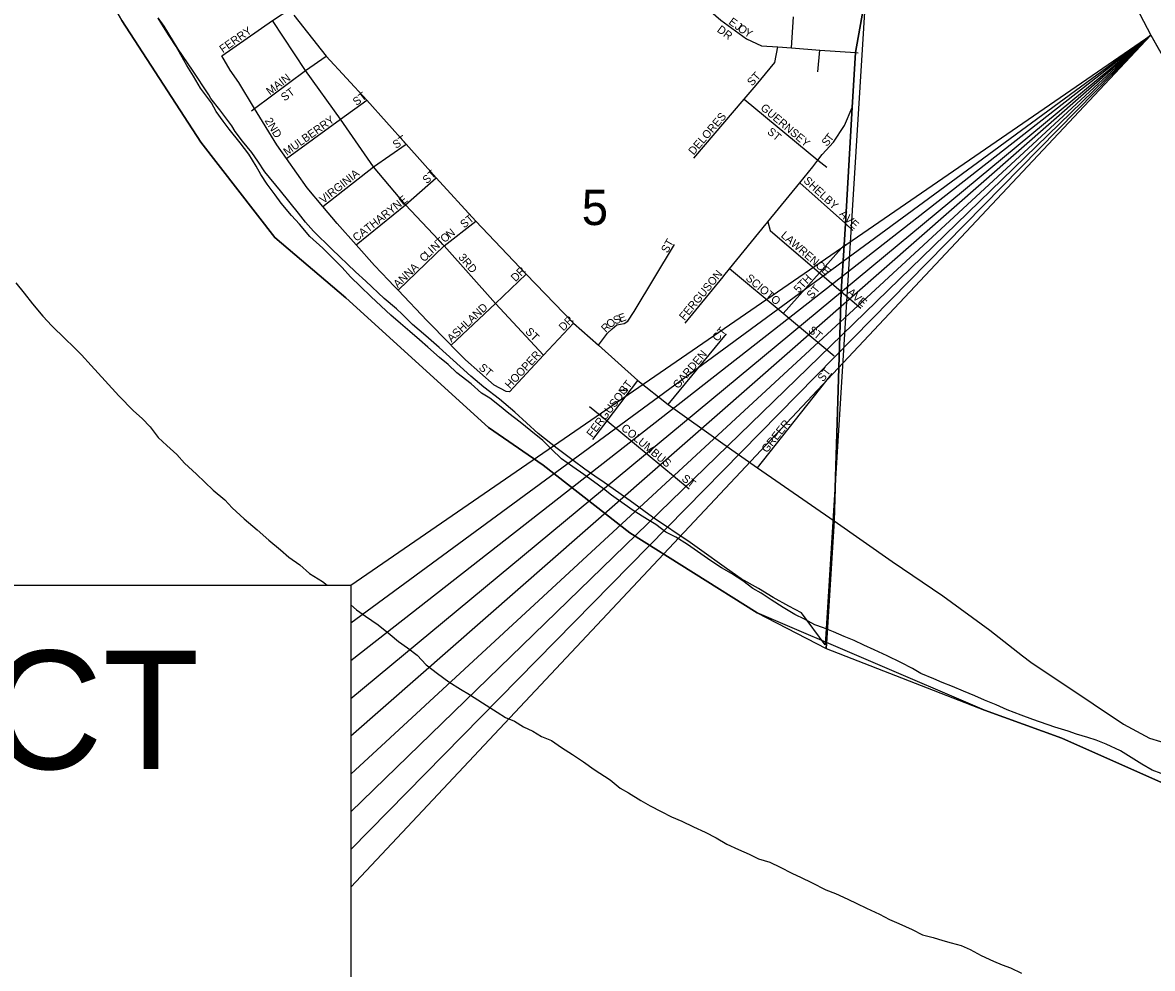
# Model space of a CAD drawing. Extents: x 0 to 34, y 0 to 22.
# Drawn here: x 3.579 to 4.916, y 14.797 to 15.917 of the extents above; entities that cross this region are included whole.
import ezdxf

# ---------------------------------------------------------------- set-up
doc = ezdxf.new("R2010")
doc.units = 0
for name, color, linetype in [('GM_X_City_Street', 7, 'Continuous'), ('GM_X_City_Street_Text', 7, 'Continuous'), ('GM_X_Corporation', 7, 'Continuous'), ('GM_X_County', 7, 'Continuous'), ('GM_X_Major_River', 7, 'Continuous'), ('GM_X_Section', 7, 'Continuous'), ('GM_X_Section_Text', 7, 'Continuous'), ('GM_X_Township', 7, 'Continuous'), ('GM_X_US_Route', 7, 'Continuous'), ('SH_Text', 7, 'Continuous')]:
    doc.layers.add(name, color=color, linetype=linetype)

msp = doc.modelspace()

# ---------------------------------------------------------------- linework, layer by layer
at = {"layer": 'GM_X_City_Street'}
for points in [[(4.3709, 15.9869), (4.3707, 15.96), (4.3788, 15.9425), (4.4051, 15.9194), (4.4355, 15.8973), (4.4532, 15.8892), (4.4727, 15.8878), (4.4889, 15.8866), (4.5222, 15.8842), (4.5644, 15.8812), (4.5676, 15.8809)], [(3.8147, 15.8773), (3.8747, 15.9191), (3.8963, 15.9332)], [(3.8997, 15.9253), (3.9381, 15.877), (3.9864, 15.8247), (4.0329, 15.7727), (4.0682, 15.7327), (4.1153, 15.6817), (4.1747, 15.6187), (4.2308, 15.5607), (4.2604, 15.5348), (4.3071, 15.4929), (4.3427, 15.4647), (4.4074, 15.4185), (4.4485, 15.3898), (4.5393, 15.3267), (4.6081, 15.2788), (4.668, 15.2381), (4.7235, 15.1974), (4.7623, 15.1671)], [(4.1954, 15.5228), (4.1384, 15.584), (4.0776, 15.6526), (4.0321, 15.7008), (3.994, 15.746), (3.9551, 15.8022), (3.9135, 15.8599), (3.8747, 15.9191)], [(4.4889, 15.8866), (4.4912, 15.9233)], [(4.3731, 15.756), (4.4328, 15.8259), (4.447, 15.8425), (4.4693, 15.8696), (4.4727, 15.8878)], [(4.0119, 15.6118), (3.9954, 15.6292), (3.9737, 15.6535), (3.9513, 15.6787), (3.9343, 15.6989), (3.9158, 15.7209), (3.8912, 15.7556), (3.8796, 15.7719), (3.8534, 15.815), (3.8349, 15.8456), (3.8245, 15.8605), (3.8147, 15.8773)], [(3.8499, 15.8124), (3.8534, 15.815), (3.9135, 15.8599), (3.9381, 15.877)], [(4.52, 15.8583), (4.5222, 15.8842)], [(3.8912, 15.7556), (3.9551, 15.8022), (3.9864, 15.8247)], [(4.4328, 15.8259), (4.5202, 15.754), (4.5307, 15.7454)], [(4.4598, 15.6794), (4.461, 15.6809), (4.4986, 15.727), (4.514, 15.746), (4.5202, 15.754), (4.5252, 15.7606), (4.5387, 15.7753), (4.5514, 15.7949), (4.5608, 15.816)], [(3.9343, 15.6989), (3.994, 15.746), (4.0329, 15.7727)], [(3.9737, 15.6535), (4.0321, 15.7008), (4.0682, 15.7327)], [(4.4986, 15.727), (4.5526, 15.6787), (4.5616, 15.6705)], [(4.0233, 15.5998), (4.0776, 15.6526), (4.1153, 15.6817)], [(4.4088, 15.617), (4.4154, 15.625), (4.459, 15.6785), (4.4598, 15.6794)], [(4.461, 15.6809), (4.4634, 15.6706), (4.5219, 15.6205), (4.5478, 15.5982), (4.5707, 15.5785)], [(4.2604, 15.5348), (4.2711, 15.549), (4.2765, 15.5542), (4.2822, 15.5589), (4.2909, 15.5606), (4.2951, 15.5633), (4.3027, 15.5747), (4.3502, 15.654)], [(4.4789, 15.5722), (4.5219, 15.6205), (4.5511, 15.6533), (4.5523, 15.6547)], [(4.0861, 15.5347), (4.1384, 15.584), (4.1747, 15.6187)], [(4.5393, 15.5219), (4.4789, 15.5722), (4.4154, 15.625)], [(4.0836, 15.5373), (4.0575, 15.5638), (4.0233, 15.5998), (4.0184, 15.605), (4.0119, 15.6118)], [(4.3631, 15.5609), (4.4079, 15.6158), (4.4088, 15.617)], [(4.1551, 15.4795), (4.1954, 15.5228), (4.2308, 15.5607)], [(4.1551, 15.4795), (4.1513, 15.4799), (4.137, 15.4873), (4.1032, 15.5173), (4.0866, 15.5342), (4.0861, 15.5347), (4.0836, 15.5373)], [(4.3427, 15.4647), (4.4119, 15.5481)], [(4.4485, 15.3898), (4.537, 15.5013)], [(4.2537, 15.4232), (4.2705, 15.4452), (4.3071, 15.4929)], [(4.2496, 15.4624), (4.2705, 15.4452), (4.3679, 15.3649)], [(4.7623, 15.1671), (4.772, 15.1595), (4.8458, 15.1102), (4.8819, 15.0861), (4.9124, 15.0698), (4.9906, 15.046), (5.0302, 15.0327), (5.0873, 15.0159), (5.1219, 15.0068), (5.1452, 15.0023)]]:
    msp.add_lwpolyline(points, dxfattribs=at)
at = {"layer": 'GM_X_Corporation'}
msp.add_lwpolyline([(4.9409, 15.0109), (4.8087, 15.0697), (4.7171, 15.1027), (4.4484, 15.218), (4.2977, 15.3128), (4.1948, 15.3929), (4.1301, 15.4372), (3.9616, 15.5909), (3.8772, 15.6623), (3.7898, 15.775), (3.6963, 15.9193), (3.6399, 16.018), (3.4223, 16.4243)], dxfattribs=at)
at = {"layer": 'GM_X_County'}
msp.add_lwpolyline([(3.4223, 16.4243), (3.6399, 16.018), (3.6963, 15.9193), (3.7898, 15.775), (3.8772, 15.6623), (3.9616, 15.5909), (4.1301, 15.4372), (4.1948, 15.3929), (4.2977, 15.3128), (4.4484, 15.218), (4.53, 15.1758), (4.7171, 15.1027), (4.8087, 15.0697), (4.9409, 15.0109), (4.9836, 14.9934), (5.1229, 14.9601), (5.2411, 14.9222), (5.3493, 14.8892), (5.4549, 14.8608), (5.5492, 14.8433), (5.6098, 14.8494), (5.8119, 14.8141), (6.1284, 14.8081)], dxfattribs=at)
at = {"layer": 'GM_X_Major_River'}
for points in [[(4.0927, 15.502), (4.0825, 15.5119), (4.0722, 15.5202), (4.0586, 15.5323), (4.0484, 15.5411), (4.0371, 15.5509), (4.0261, 15.5604), (4.0148, 15.5703), (4.0031, 15.5809), (3.991, 15.5923), (3.9789, 15.6044), (3.9671, 15.6158), (3.9569, 15.6268), (3.9441, 15.6397), (3.9343, 15.6496), (3.9188, 15.6636), (3.9067, 15.678), (3.8972, 15.6883), (3.8847, 15.7031), (3.8776, 15.7126), (3.8685, 15.7255), (3.8609, 15.7369), (3.8552, 15.7467), (3.8466, 15.7611), (3.8364, 15.7744), (3.8235, 15.7904), (3.8163, 15.7998), (3.808, 15.8116), (3.8023, 15.8215), (3.7895, 15.8389), (3.7812, 15.8534), (3.7732, 15.8659), (3.766, 15.8784), (3.7608, 15.8883), (3.7524, 15.9008), (3.7456, 15.9118), (3.7392, 15.9217)], [(3.5708, 15.6086), (3.5807, 15.5965), (3.5905, 15.5839), (3.603, 15.5691), (3.6136, 15.5578), (3.6294, 15.5422), (3.6393, 15.5327), (3.6487, 15.5232), (3.6601, 15.5107), (3.6767, 15.4925), (3.6929, 15.4747), (3.7103, 15.4572), (3.7202, 15.4481), (3.73, 15.4383), (3.7394, 15.4257), (3.7497, 15.4159), (3.7614, 15.4053), (3.7704, 15.395), (3.7848, 15.3821), (3.8045, 15.3631), (3.8181, 15.3518), (3.8268, 15.3423), (3.8411, 15.3294), (3.8563, 15.3161), (3.8702, 15.304), (3.8839, 15.2926), (3.8941, 15.2839), (3.9069, 15.2747), (3.9186, 15.2645), (3.9338, 15.255), (3.9392, 15.2507)], [(4.9264, 15.0279), (4.9158, 15.0316), (4.9033, 15.0389), (4.8908, 15.0468), (4.878, 15.0548), (4.8614, 15.0627), (4.8493, 15.0673), (4.8394, 15.0703), (4.8262, 15.0745), (4.8164, 15.0779), (4.8005, 15.0828), (4.7744, 15.0916), (4.7608, 15.0969), (4.7441, 15.1033), (4.7309, 15.109), (4.7173, 15.1147), (4.7059, 15.1196), (4.6923, 15.1253), (4.6795, 15.1306), (4.667, 15.1356), (4.6572, 15.1397), (4.642, 15.1462), (4.6322, 15.1519), (4.6182, 15.1591), (4.6019, 15.167), (4.5868, 15.1742), (4.5743, 15.1796), (4.563, 15.1852), (4.5513, 15.1898), (4.5384, 15.1955), (4.5267, 15.2004), (4.5165, 15.2038), (4.5044, 15.2103), (4.4927, 15.216), (4.4791, 15.2243), (4.4647, 15.2334), (4.453, 15.2414), (4.4431, 15.2467), (4.4314, 15.2558), (4.4178, 15.2645), (4.4061, 15.2713), (4.3932, 15.2797), (4.3815, 15.2877), (4.3656, 15.2987), (4.352, 15.3074), (4.3403, 15.3134), (4.3282, 15.3226), (4.3184, 15.3286), (4.3014, 15.3392), (4.2908, 15.3468), (4.276, 15.3571), (4.2662, 15.3647), (4.2545, 15.3734), (4.2431, 15.3817), (4.2299, 15.3908), (4.2167, 15.4003), (4.2049, 15.4117), (4.1947, 15.4219), (4.1804, 15.4333), (4.1679, 15.4436), (4.1543, 15.4538), (4.1433, 15.4629), (4.132, 15.472), (4.1221, 15.4781), (4.1097, 15.4891), (4.0927, 15.502)], [(3.9674, 15.2274), (3.9742, 15.2216), (3.9848, 15.2141), (3.9995, 15.2038), (4.0139, 15.1924), (4.0237, 15.1841), (4.0343, 15.1765), (4.046, 15.1678), (4.0563, 15.1564), (4.0699, 15.1462), (4.0835, 15.1363), (4.0971, 15.1276), (4.1077, 15.1215), (4.1232, 15.1116), (4.1406, 15.1006), (4.1504, 15.0942), (4.161, 15.0896), (4.1716, 15.0832), (4.1829, 15.0779), (4.1931, 15.0718), (4.2048, 15.0669), (4.2166, 15.0585), (4.2298, 15.0502), (4.2426, 15.0415), (4.2555, 15.0324), (4.2744, 15.0202), (4.2861, 15.0104), (4.296, 15.005), (4.3107, 14.9959), (4.3217, 14.9895), (4.3345, 14.983), (4.347, 14.9766), (4.3591, 14.9713), (4.3727, 14.9648), (4.3867, 14.9584), (4.3996, 14.9516), (4.4124, 14.944), (4.426, 14.9379), (4.4389, 14.9322), (4.4498, 14.9269), (4.4631, 14.9227), (4.4756, 14.9171), (4.4892, 14.9098), (4.5001, 14.9049), (4.5126, 14.8988), (4.5296, 14.8901), (4.541, 14.8856), (4.5557, 14.8791), (4.5663, 14.8738), (4.5776, 14.8685), (4.5928, 14.8613), (4.6049, 14.8549), (4.6158, 14.8503), (4.6317, 14.8431), (4.6438, 14.837), (4.6563, 14.8336), (4.668, 14.8302), (4.6779, 14.8272), (4.6896, 14.8241), (4.7002, 14.8196), (4.7134, 14.8124), (4.7278, 14.8056), (4.738, 14.8014), (4.7482, 14.7976), (4.761, 14.7915)]]:
    msp.add_lwpolyline(points, dxfattribs=at)
at = {"layer": 'GM_X_Section'}
msp.add_lwpolyline([(4.5788, 15.9866), (4.5286, 15.1803), (4.5006, 15.2178), (4.4855, 15.2258), (4.4673, 15.2361), (4.4499, 15.2467), (4.4294, 15.2584), (4.412, 15.2706), (4.3798, 15.2933), (4.3688, 15.3013), (4.3245, 15.3313), (4.298, 15.3506), (4.2673, 15.3722), (4.256, 15.3798), (4.2442, 15.3881), (4.2306, 15.3984), (4.2117, 15.4124), (4.189, 15.4302), (4.1613, 15.4556), (4.1431, 15.4708), (4.1246, 15.4852), (4.1094, 15.4981), (4.0966, 15.5095), (4.072, 15.5319), (4.0561, 15.5459), (4.0405, 15.5592), (4.028, 15.5717), (4.0212, 15.5777), (4.0068, 15.5899), (3.9852, 15.6107), (3.9727, 15.6217), (3.9447, 15.6486), (3.9232, 15.6699), (3.9137, 15.6805), (3.9054, 15.6911), (3.8842, 15.7176), (3.8656, 15.74), (3.8573, 15.7525), (3.8501, 15.7628), (3.8391, 15.7764), (3.8304, 15.7878), (3.8266, 15.7946), (3.8122, 15.8132), (3.8016, 15.8268), (3.7994, 15.831), (3.7801, 15.8602), (3.763, 15.8852), (3.7464, 15.9125), (3.7392, 15.9223)], dxfattribs=at)
at = {"layer": 'GM_X_Township'}
for points in [[(4.6299, 17.0103), (4.5943, 16.4014), (4.6029, 16.3572), (4.6, 16.334), (4.5986, 16.2926), (4.5946, 16.2313), (4.5919, 16.1816), (4.5915, 16.174), (4.5876, 16.1027), (4.5828, 15.9836), (4.5644, 15.8812), (4.5608, 15.816), (4.5526, 15.6787), (4.5511, 15.6533), (4.5478, 15.5982), (4.5393, 15.3267), (4.53, 15.1758), (4.7171, 15.1027), (4.8087, 15.0697), (4.9409, 15.0109)], [(3.6963, 15.9193), (3.7898, 15.775), (3.8772, 15.6623), (3.9616, 15.5909), (4.1301, 15.4372), (4.1948, 15.3929), (4.2977, 15.3128), (4.4484, 15.218), (4.53, 15.1758), (4.5393, 15.3267), (4.5478, 15.5982), (4.5511, 15.6533), (4.5526, 15.6787), (4.5608, 15.816), (4.5644, 15.8812), (4.5828, 15.9836)]]:
    msp.add_lwpolyline(points, dxfattribs=at)
at = {"layer": 'GM_X_US_Route'}
for points in [[(4.8309, 16.0512), (4.8399, 16.0369), (4.8834, 15.9611), (4.9139, 15.9017), (4.9358, 15.8635), (4.9701, 15.8096), (4.9839, 15.791), (5.0221, 15.7512), (5.0502, 15.7273), (5.0757, 15.7119), (5.1054, 15.697), (5.1373, 15.6832), (5.2153, 15.654), (5.2817, 15.6306), (5.3172, 15.6152), (5.3507, 15.5945), (5.4554, 15.4954), (5.5676, 15.398), (5.6488, 15.3249)], [(4.9139, 15.9017), (4.921, 15.8893), (4.9358, 15.8635), (4.9579, 15.8288)]]:
    msp.add_lwpolyline(points, dxfattribs=at)
at = {"layer": 'SH_Text'}
msp.add_line((3.9674, 14.9378), (4.9139, 15.9017), dxfattribs=at)
for points in [[(3.9674, 15.2507), (4.9139, 15.9017), (3.9674, 14.8931)], [(3.9674, 15.206), (4.9139, 15.9017), (3.9674, 15.1613)], [(3.9674, 15.1166), (4.9139, 15.9017), (3.9674, 15.0719)], [(3.9674, 15.0272), (4.9139, 15.9017), (3.9674, 14.9825)]]:
    msp.add_lwpolyline(points, dxfattribs=at)
msp.add_lwpolyline([(2.178, 15.2507), (3.9674, 15.2507), (3.9674, 14.5355), (2.178, 14.5355)], close=True, dxfattribs=at)

# ---------------------------------------------------------------- texts
at = {"layer": 'GM_X_City_Street_Text'}
for s, rotation, p in [('FERRY', 35.094, (3.8159, 15.8803)), ('DR', 323.1345, (4.3999, 15.9066)), ('E', 323.9242, (4.4136, 15.9157)), ('J', 323.8995, (4.421, 15.9103)), ('O', 323.912, (4.4243, 15.9078)), ('Y', 329.331, (4.4319, 15.9024)), ('ST', 47.4955, (4.4422, 15.8409)), ('MAIN', 37.1854, (3.8716, 15.8303)), ('ST', 36.867, (3.8889, 15.8231)), ('ST', 37.5756, (3.9741, 15.8178)), ('GUERNSEY', 319.8986, (4.4514, 15.8144)), ('2ND', 301.3286, (3.8651, 15.8006)), ('MULBERRY', 35.5378, (3.8917, 15.7587)), ('DELORES', 49.4994, (4.373, 15.7592)), ('ST', 320.1969, (4.4593, 15.7861)), ('ST', 34.6943, (4.0209, 15.767)), ('S', 49.2061, (4.5306, 15.7693)), ('T', 52.6796, (4.5353, 15.7748)), ('VIRGINIA', 38.5169, (3.9349, 15.7019)), ('ST', 42.5078, (4.0573, 15.7252)), ('SHELBY', 317.2319, (4.5023, 15.7285)), ('CATHARYNE', 38.3466, (3.9741, 15.657)), ('ST', 39.8121, (4.1016, 15.6728)), ('A', 315.0724, (4.5448, 15.6893)), ('V', 316.2898, (4.5509, 15.6833)), ('N', 38.284, (4.0845, 15.6607)), ('E', 317.6715, (4.5571, 15.6773)), ('N', 43.8699, (4.0672, 15.6454)), ('T', 41.8864, (4.0731, 15.6511)), ('O', 38.7737, (4.078, 15.6555)), ('ST', 60.2572, (4.342, 15.6431)), ('LAWRENCE', 319.2357, (4.4755, 15.6636)), ('C', 43.8704, (4.054, 15.6327)), ('L', 43.8793, (4.0594, 15.6379)), ('I', 43.8852, (4.0642, 15.6425)), ('ANNA', 43.9956, (4.0231, 15.6018)), ('3RD', 310.3617, (4.0941, 15.6384)), ('DR', 44.9989, (4.1623, 15.6093)), ('FERGUSON', 50.6008, (4.3622, 15.5634)), ('SCIOTO', 319.8978, (4.4339, 15.6128)), ('5TH', 46.6395, (4.4973, 15.5959)), ('ST', 50.1994, (4.513, 15.5888)), ('AVE', 319.1889, (4.5539, 15.5961)), ('ASHLAND', 43.1522, (4.0865, 15.5377)), ('DR', 44.9989, (4.219, 15.551)), ('O', 40.0672, (4.2743, 15.5543)), ('S', 20.5768, (4.2799, 15.5592)), ('E', 19.6189, (4.2861, 15.5616)), ('ST', 314.9941, (4.1731, 15.5501)), ('R', 43.0854, (4.2689, 15.5493)), ('CT', 49.7596, (4.4013, 15.5384)), ('ST', 320.1969, (4.508, 15.5511)), ('HOOPER', 47.1761, (4.1556, 15.4826)), ('GARDEN', 49.9373, (4.3547, 15.4825)), ('ST', 320.1969, (4.118, 15.5069)), ('ST', 52.4361, (4.5263, 15.4908)), ('FERGUSON', 52.8165, (4.2529, 15.4249)), ('ST', 52.4255, (4.2913, 15.4758)), ('GREER', 51.1473, (4.4597, 15.4067)), ('COLUMBUS', 320.291, (4.2864, 15.4353)), ('ST', 322.4244, (4.358, 15.3753))]:
    msp.add_text(s, height=0.00947, rotation=rotation, dxfattribs=at).set_placement(p)
at = {"layer": 'GM_X_Section_Text'}
msp.add_text('5', height=0.0419, rotation=0, dxfattribs=at).set_placement((4.2406, 15.677))
at = {"layer": 'SH_Text'}
msp.add_text('BEGIN PROJECT', height=0.14, dxfattribs=at).set_placement((2.2797, 15.0331))

doc.saveas('drawing.dxf')
